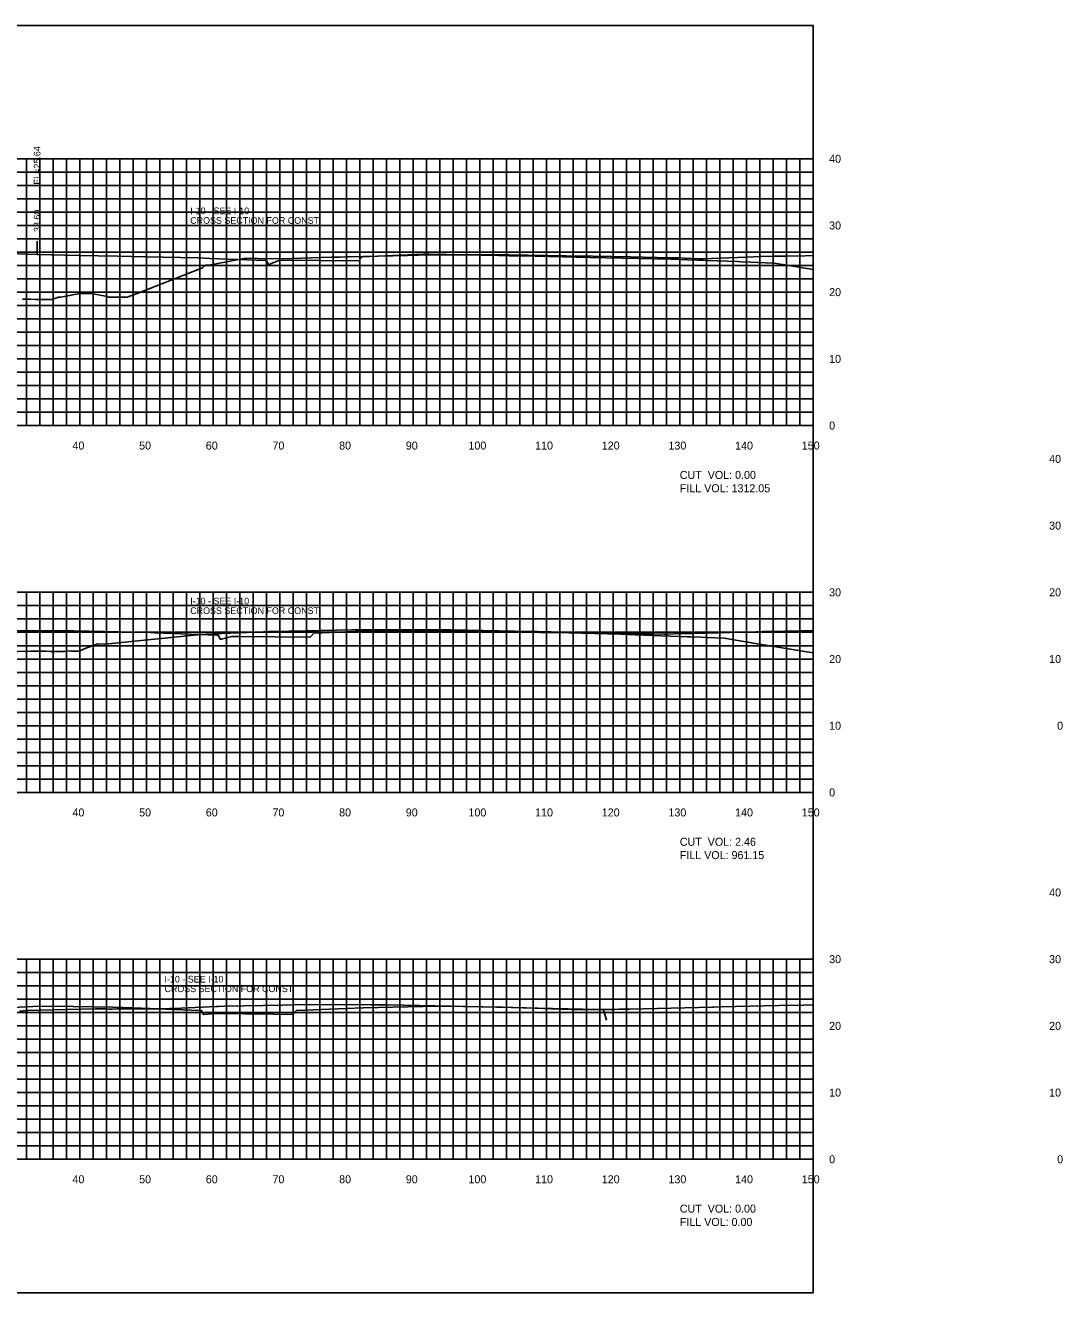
# Model space of a CAD drawing. Extents: x 1797518 to 1804843, y 248068 to 251132.
# Drawn here: x 1802322.8 to 1802478.4, y 250079.4 to 250269.4 of the extents above; entities that cross this region are included whole.
import ezdxf

# ---------------------------------------------------------------- set-up
doc = ezdxf.new("R2010")
doc.units = 0
for name, color, linetype in [('10', 7, 'Continuous'), ('3', 7, 'Continuous'), ('31', 7, 'Continuous'), ('60', 7, 'Continuous'), ('ANNO-TXT', 7, 'Continuous'), ('CL-CNST', 7, 'Continuous'), ('Level 62', 7, 'Continuous'), ('M-ROADS', 7, 'Continuous')]:
    doc.layers.add(name, color=color, linetype=linetype)

msp = doc.modelspace()

# ---------------------------------------------------------------- linework, layer by layer
msp.add_line((1802324.6, 250235.07), (1802324.6, 250237.07))
msp.add_lwpolyline([(1802141, 250079.43), (1802441, 250079.43), (1802441, 250269.43), (1802141, 250269.43)], close=True)
at = {"layer": '60'}
for p, q in [((1802441, 250209.43), (1802441, 250249.43)), ((1802441.06, 250249.43), (1802441, 250249.43)), ((1802441.06, 250239.43), (1802441, 250239.43)), ((1802441.06, 250229.43), (1802441, 250229.43)), ((1802441.06, 250219.43), (1802441, 250219.43)), ((1802141, 250209.43), (1802441, 250209.43)), ((1802331, 250209.37), (1802331, 250209.43)), ((1802341, 250209.37), (1802341, 250209.43)), ((1802351, 250209.37), (1802351, 250209.43)), ((1802361, 250209.37), (1802361, 250209.43)), ((1802371, 250209.37), (1802371, 250209.43)), ((1802381, 250209.37), (1802381, 250209.43)), ((1802391, 250209.37), (1802391, 250209.43)), ((1802401, 250209.37), (1802401, 250209.43)), ((1802411, 250209.37), (1802411, 250209.43)), ((1802421, 250209.37), (1802421, 250209.43)), ((1802431, 250209.37), (1802431, 250209.43)), ((1802441, 250209.37), (1802441, 250209.43)), ((1802441.06, 250209.43), (1802441, 250209.43)), ((1802441, 250154.43), (1802441, 250184.43)), ((1802441.06, 250184.43), (1802441, 250184.43)), ((1802441.06, 250174.43), (1802441, 250174.43)), ((1802441.06, 250164.43), (1802441, 250164.43)), ((1802141, 250154.43), (1802441, 250154.43)), ((1802331, 250154.37), (1802331, 250154.43)), ((1802341, 250154.37), (1802341, 250154.43)), ((1802351, 250154.37), (1802351, 250154.43)), ((1802361, 250154.37), (1802361, 250154.43)), ((1802371, 250154.37), (1802371, 250154.43)), ((1802381, 250154.37), (1802381, 250154.43)), ((1802391, 250154.37), (1802391, 250154.43)), ((1802401, 250154.37), (1802401, 250154.43)), ((1802411, 250154.37), (1802411, 250154.43)), ((1802421, 250154.37), (1802421, 250154.43)), ((1802431, 250154.37), (1802431, 250154.43)), ((1802441, 250154.37), (1802441, 250154.43)), ((1802441.06, 250154.43), (1802441, 250154.43)), ((1802441, 250099.43), (1802441, 250129.43)), ((1802441.06, 250129.43), (1802441, 250129.43)), ((1802441.06, 250119.43), (1802441, 250119.43)), ((1802441.06, 250109.43), (1802441, 250109.43)), ((1802141, 250099.43), (1802441, 250099.43)), ((1802331, 250099.37), (1802331, 250099.43)), ((1802341, 250099.37), (1802341, 250099.43)), ((1802351, 250099.37), (1802351, 250099.43)), ((1802361, 250099.37), (1802361, 250099.43)), ((1802371, 250099.37), (1802371, 250099.43)), ((1802381, 250099.37), (1802381, 250099.43)), ((1802391, 250099.37), (1802391, 250099.43)), ((1802401, 250099.37), (1802401, 250099.43)), ((1802411, 250099.37), (1802411, 250099.43)), ((1802421, 250099.37), (1802421, 250099.43)), ((1802431, 250099.37), (1802431, 250099.43)), ((1802441, 250099.37), (1802441, 250099.43)), ((1802441.06, 250099.43), (1802441, 250099.43))]:
    msp.add_line(p, q, dxfattribs=at)
at = {"layer": 'CL-CNST'}
for points in [[(1802257.69, 250228.09), (1802281, 250233.91), (1802283, 250233.99), (1802291, 250234.31), (1802315, 250235.21), (1802319, 250235.3), (1802324.6, 250235.07)], [(1802324.6, 250235.07), (1802330.86, 250234.94), (1802336.66, 250234.82), (1802340.83, 250234.74), (1802348.73, 250234.57), (1802350.5, 250234.5), (1802358.78, 250234.19), (1802358.78, 250234.19), (1802358.99, 250234.18), (1802359, 250234.16), (1802359.32, 250233.57), (1802359.36, 250233.59), (1802360.59, 250234.06), (1802361.04, 250234.23), (1802361.04, 250234.23), (1802361.06, 250234.23), (1802372.81, 250234.12), (1802373.32, 250234.7), (1802373.35, 250234.73), (1802382.52, 250235.11), (1802383.41, 250235.14), (1802393.85, 250234.93), (1802395.47, 250234.89), (1802397.26, 250234.86), (1802407.53, 250234.65), (1802409.94, 250234.6), (1802419.59, 250234.4), (1802422.1, 250234.3), (1802429.65, 250234.01), (1802430.21, 250233.99), (1802431.66, 250233.93), (1802432.69, 250233.89), (1802435.18, 250233.8), (1802441, 250232.84)], [(1802317.54, 250178.67), (1802329.54, 250178.65), (1802330.1, 250178.63), (1802341.55, 250178.39), (1802342.26, 250178.36), (1802351.56, 250178), (1802351.58, 250177.99), (1802351.8, 250177.99), (1802351.82, 250177.93), (1802352.11, 250177.38), (1802352.26, 250177.43), (1802353.82, 250177.81), (1802354.95, 250177.79), (1802365.54, 250177.69), (1802365.6, 250177.76), (1802366.08, 250178.3), (1802367.29, 250178.35), (1802376.09, 250178.71), (1802377.8, 250178.7), (1802388.11, 250178.68), (1802390.11, 250178.64), (1802400.12, 250178.42), (1802402.41, 250178.38), (1802412.14, 250178.17), (1802414.28, 250178.08), (1802422.15, 250177.77), (1802422.61, 250177.76), (1802424.15, 250177.7), (1802424.98, 250177.66), (1802427.66, 250177.56), (1802432.94, 250176.68), (1802441, 250175.34)], [(1802315, 250121.89), (1802323.96, 250122.34), (1802327, 250122.4), (1802335.96, 250122.21), (1802339, 250122.14), (1802346.47, 250121.84), (1802349, 250121.74), (1802349.19, 250121.73), (1802349.25, 250121.73), (1802349.47, 250121.28), (1802349.54, 250121.13), (1802350.82, 250121.22), (1802351.25, 250121.26), (1802359.99, 250121.16), (1802362.96, 250121.13), (1802363.1, 250121.29), (1802363.5, 250121.75), (1802370.97, 250122.04), (1802373.5, 250122.15), (1802382.46, 250122.34), (1802385.5, 250122.4), (1802394.46, 250122.21), (1802397.5, 250122.14), (1802406.46, 250121.94), (1802409.5, 250121.88), (1802409.63, 250121.47), (1802410.01, 250120.28)]]:
    msp.add_lwpolyline(points, dxfattribs=at)
at = {"layer": 'Level 62'}
for p, q in [((1802141, 250249.43), (1802441, 250249.43)), ((1802323, 250209.43), (1802323, 250249.43)), ((1802325, 250209.43), (1802325, 250249.43)), ((1802327, 250209.43), (1802327, 250249.43)), ((1802329, 250209.43), (1802329, 250249.43)), ((1802331, 250209.43), (1802331, 250249.43)), ((1802333, 250209.43), (1802333, 250249.43)), ((1802335, 250209.43), (1802335, 250249.43)), ((1802337, 250209.43), (1802337, 250249.43)), ((1802339, 250209.43), (1802339, 250249.43)), ((1802341, 250209.43), (1802341, 250249.43)), ((1802343, 250209.43), (1802343, 250249.43)), ((1802345, 250209.43), (1802345, 250249.43)), ((1802347, 250209.43), (1802347, 250249.43)), ((1802349, 250209.43), (1802349, 250249.43)), ((1802351, 250209.43), (1802351, 250249.43)), ((1802353, 250209.43), (1802353, 250249.43)), ((1802355, 250209.43), (1802355, 250249.43)), ((1802357, 250209.43), (1802357, 250249.43)), ((1802359, 250209.43), (1802359, 250249.43)), ((1802361, 250209.43), (1802361, 250249.43)), ((1802363, 250209.43), (1802363, 250249.43)), ((1802365, 250209.43), (1802365, 250249.43)), ((1802367, 250209.43), (1802367, 250249.43)), ((1802369, 250209.43), (1802369, 250249.43)), ((1802371, 250209.43), (1802371, 250249.43)), ((1802373, 250209.43), (1802373, 250249.43)), ((1802375, 250209.43), (1802375, 250249.43)), ((1802377, 250209.43), (1802377, 250249.43)), ((1802379, 250209.43), (1802379, 250249.43)), ((1802381, 250209.43), (1802381, 250249.43)), ((1802383, 250209.43), (1802383, 250249.43)), ((1802385, 250209.43), (1802385, 250249.43)), ((1802387, 250209.43), (1802387, 250249.43)), ((1802389, 250209.43), (1802389, 250249.43)), ((1802391, 250209.43), (1802391, 250249.43)), ((1802393, 250209.43), (1802393, 250249.43)), ((1802395, 250209.43), (1802395, 250249.43)), ((1802397, 250209.43), (1802397, 250249.43)), ((1802399, 250209.43), (1802399, 250249.43)), ((1802401, 250209.43), (1802401, 250249.43)), ((1802403, 250209.43), (1802403, 250249.43)), ((1802405, 250209.43), (1802405, 250249.43)), ((1802407, 250209.43), (1802407, 250249.43)), ((1802409, 250209.43), (1802409, 250249.43)), ((1802411, 250209.43), (1802411, 250249.43)), ((1802413, 250209.43), (1802413, 250249.43)), ((1802415, 250209.43), (1802415, 250249.43)), ((1802417, 250209.43), (1802417, 250249.43)), ((1802419, 250209.43), (1802419, 250249.43)), ((1802421, 250209.43), (1802421, 250249.43)), ((1802423, 250209.43), (1802423, 250249.43)), ((1802425, 250209.43), (1802425, 250249.43)), ((1802427, 250209.43), (1802427, 250249.43)), ((1802429, 250209.43), (1802429, 250249.43)), ((1802431, 250209.43), (1802431, 250249.43)), ((1802433, 250209.43), (1802433, 250249.43)), ((1802435, 250209.43), (1802435, 250249.43)), ((1802437, 250209.43), (1802437, 250249.43)), ((1802439, 250209.43), (1802439, 250249.43)), ((1802441, 250209.43), (1802441, 250249.43)), ((1802141, 250247.43), (1802441, 250247.43)), ((1802141, 250245.43), (1802441, 250245.43)), ((1802141, 250243.43), (1802441, 250243.43)), ((1802141, 250241.43), (1802441, 250241.43)), ((1802141, 250239.43), (1802441, 250239.43)), ((1802141, 250237.43), (1802441, 250237.43)), ((1802141, 250235.43), (1802441, 250235.43)), ((1802141, 250233.43), (1802441, 250233.43)), ((1802141, 250231.43), (1802441, 250231.43)), ((1802141, 250229.43), (1802441, 250229.43)), ((1802141, 250227.43), (1802441, 250227.43)), ((1802141, 250225.43), (1802441, 250225.43)), ((1802141, 250223.43), (1802441, 250223.43)), ((1802141, 250221.43), (1802441, 250221.43)), ((1802141, 250219.43), (1802441, 250219.43)), ((1802141, 250217.43), (1802441, 250217.43)), ((1802141, 250215.43), (1802441, 250215.43)), ((1802141, 250213.43), (1802441, 250213.43)), ((1802141, 250211.43), (1802441, 250211.43)), ((1802141, 250209.43), (1802441, 250209.43)), ((1802141, 250184.43), (1802441, 250184.43)), ((1802323, 250154.43), (1802323, 250184.43)), ((1802325, 250154.43), (1802325, 250184.43)), ((1802327, 250154.43), (1802327, 250184.43)), ((1802329, 250154.43), (1802329, 250184.43)), ((1802331, 250154.43), (1802331, 250184.43)), ((1802333, 250154.43), (1802333, 250184.43)), ((1802335, 250154.43), (1802335, 250184.43)), ((1802337, 250154.43), (1802337, 250184.43)), ((1802339, 250154.43), (1802339, 250184.43)), ((1802341, 250154.43), (1802341, 250184.43)), ((1802343, 250154.43), (1802343, 250184.43)), ((1802345, 250154.43), (1802345, 250184.43)), ((1802347, 250154.43), (1802347, 250184.43)), ((1802349, 250154.43), (1802349, 250184.43)), ((1802351, 250154.43), (1802351, 250184.43)), ((1802353, 250154.43), (1802353, 250184.43)), ((1802355, 250154.43), (1802355, 250184.43)), ((1802357, 250154.43), (1802357, 250184.43)), ((1802359, 250154.43), (1802359, 250184.43)), ((1802361, 250154.43), (1802361, 250184.43)), ((1802363, 250154.43), (1802363, 250184.43)), ((1802365, 250154.43), (1802365, 250184.43)), ((1802367, 250154.43), (1802367, 250184.43)), ((1802369, 250154.43), (1802369, 250184.43)), ((1802371, 250154.43), (1802371, 250184.43)), ((1802373, 250154.43), (1802373, 250184.43)), ((1802375, 250154.43), (1802375, 250184.43)), ((1802377, 250154.43), (1802377, 250184.43)), ((1802379, 250154.43), (1802379, 250184.43)), ((1802381, 250154.43), (1802381, 250184.43)), ((1802383, 250154.43), (1802383, 250184.43)), ((1802385, 250154.43), (1802385, 250184.43)), ((1802387, 250154.43), (1802387, 250184.43)), ((1802389, 250154.43), (1802389, 250184.43)), ((1802391, 250154.43), (1802391, 250184.43)), ((1802393, 250154.43), (1802393, 250184.43)), ((1802395, 250154.43), (1802395, 250184.43)), ((1802397, 250154.43), (1802397, 250184.43)), ((1802399, 250154.43), (1802399, 250184.43)), ((1802401, 250154.43), (1802401, 250184.43)), ((1802403, 250154.43), (1802403, 250184.43)), ((1802405, 250154.43), (1802405, 250184.43)), ((1802407, 250154.43), (1802407, 250184.43)), ((1802409, 250154.43), (1802409, 250184.43)), ((1802411, 250154.43), (1802411, 250184.43)), ((1802413, 250154.43), (1802413, 250184.43)), ((1802415, 250154.43), (1802415, 250184.43)), ((1802417, 250154.43), (1802417, 250184.43)), ((1802419, 250154.43), (1802419, 250184.43)), ((1802421, 250154.43), (1802421, 250184.43)), ((1802423, 250154.43), (1802423, 250184.43)), ((1802425, 250154.43), (1802425, 250184.43)), ((1802427, 250154.43), (1802427, 250184.43)), ((1802429, 250154.43), (1802429, 250184.43)), ((1802431, 250154.43), (1802431, 250184.43)), ((1802433, 250154.43), (1802433, 250184.43)), ((1802435, 250154.43), (1802435, 250184.43)), ((1802437, 250154.43), (1802437, 250184.43)), ((1802439, 250154.43), (1802439, 250184.43)), ((1802441, 250154.43), (1802441, 250184.43)), ((1802141, 250182.43), (1802441, 250182.43)), ((1802141, 250180.43), (1802441, 250180.43)), ((1802141, 250178.43), (1802441, 250178.43)), ((1802141, 250176.43), (1802441, 250176.43)), ((1802141, 250174.43), (1802441, 250174.43)), ((1802141, 250172.43), (1802441, 250172.43)), ((1802141, 250170.43), (1802441, 250170.43)), ((1802141, 250168.43), (1802441, 250168.43)), ((1802141, 250166.43), (1802441, 250166.43)), ((1802141, 250164.43), (1802441, 250164.43)), ((1802141, 250162.43), (1802441, 250162.43)), ((1802141, 250160.43), (1802441, 250160.43)), ((1802141, 250158.43), (1802441, 250158.43)), ((1802141, 250156.43), (1802441, 250156.43)), ((1802141, 250154.43), (1802441, 250154.43)), ((1802141, 250129.43), (1802441, 250129.43)), ((1802323, 250099.43), (1802323, 250129.43)), ((1802325, 250099.43), (1802325, 250129.43)), ((1802327, 250099.43), (1802327, 250129.43)), ((1802329, 250099.43), (1802329, 250129.43)), ((1802331, 250099.43), (1802331, 250129.43)), ((1802333, 250099.43), (1802333, 250129.43)), ((1802335, 250099.43), (1802335, 250129.43)), ((1802337, 250099.43), (1802337, 250129.43)), ((1802339, 250099.43), (1802339, 250129.43)), ((1802341, 250099.43), (1802341, 250129.43)), ((1802343, 250099.43), (1802343, 250129.43)), ((1802345, 250099.43), (1802345, 250129.43)), ((1802347, 250099.43), (1802347, 250129.43)), ((1802349, 250099.43), (1802349, 250129.43)), ((1802351, 250099.43), (1802351, 250129.43)), ((1802353, 250099.43), (1802353, 250129.43)), ((1802355, 250099.43), (1802355, 250129.43)), ((1802357, 250099.43), (1802357, 250129.43)), ((1802359, 250099.43), (1802359, 250129.43)), ((1802361, 250099.43), (1802361, 250129.43)), ((1802363, 250099.43), (1802363, 250129.43)), ((1802365, 250099.43), (1802365, 250129.43)), ((1802367, 250099.43), (1802367, 250129.43)), ((1802369, 250099.43), (1802369, 250129.43)), ((1802371, 250099.43), (1802371, 250129.43)), ((1802373, 250099.43), (1802373, 250129.43)), ((1802375, 250099.43), (1802375, 250129.43)), ((1802377, 250099.43), (1802377, 250129.43)), ((1802379, 250099.43), (1802379, 250129.43)), ((1802381, 250099.43), (1802381, 250129.43)), ((1802383, 250099.43), (1802383, 250129.43)), ((1802385, 250099.43), (1802385, 250129.43)), ((1802387, 250099.43), (1802387, 250129.43)), ((1802389, 250099.43), (1802389, 250129.43)), ((1802391, 250099.43), (1802391, 250129.43)), ((1802393, 250099.43), (1802393, 250129.43)), ((1802395, 250099.43), (1802395, 250129.43)), ((1802397, 250099.43), (1802397, 250129.43)), ((1802399, 250099.43), (1802399, 250129.43)), ((1802401, 250099.43), (1802401, 250129.43)), ((1802403, 250099.43), (1802403, 250129.43)), ((1802405, 250099.43), (1802405, 250129.43)), ((1802407, 250099.43), (1802407, 250129.43)), ((1802409, 250099.43), (1802409, 250129.43)), ((1802411, 250099.43), (1802411, 250129.43)), ((1802413, 250099.43), (1802413, 250129.43)), ((1802415, 250099.43), (1802415, 250129.43)), ((1802417, 250099.43), (1802417, 250129.43)), ((1802419, 250099.43), (1802419, 250129.43)), ((1802421, 250099.43), (1802421, 250129.43)), ((1802423, 250099.43), (1802423, 250129.43)), ((1802425, 250099.43), (1802425, 250129.43)), ((1802427, 250099.43), (1802427, 250129.43)), ((1802429, 250099.43), (1802429, 250129.43)), ((1802431, 250099.43), (1802431, 250129.43)), ((1802433, 250099.43), (1802433, 250129.43)), ((1802435, 250099.43), (1802435, 250129.43)), ((1802437, 250099.43), (1802437, 250129.43)), ((1802439, 250099.43), (1802439, 250129.43)), ((1802441, 250099.43), (1802441, 250129.43)), ((1802141, 250127.43), (1802441, 250127.43)), ((1802141, 250125.43), (1802441, 250125.43)), ((1802141, 250123.43), (1802441, 250123.43)), ((1802141, 250121.43), (1802441, 250121.43)), ((1802141, 250119.43), (1802441, 250119.43)), ((1802141, 250117.43), (1802441, 250117.43)), ((1802141, 250115.43), (1802441, 250115.43)), ((1802141, 250113.43), (1802441, 250113.43)), ((1802141, 250111.43), (1802441, 250111.43)), ((1802141, 250109.43), (1802441, 250109.43)), ((1802141, 250107.43), (1802441, 250107.43)), ((1802141, 250105.43), (1802441, 250105.43)), ((1802141, 250103.43), (1802441, 250103.43)), ((1802141, 250101.43), (1802441, 250101.43)), ((1802141, 250099.43), (1802441, 250099.43))]:
    msp.add_line(p, q, dxfattribs=at)
at = {"layer": 'M-ROADS'}
for points in [[(1802322.4, 250228.4), (1802323.49, 250228.39), (1802323.66, 250228.38), (1802324.36, 250228.35), (1802324.49, 250228.32), (1802324.97, 250228.31), (1802325.93, 250228.34), (1802326.3, 250228.34), (1802326.87, 250228.35), (1802327.81, 250228.68), (1802328.16, 250228.69), (1802330.99, 250229.21), (1802331.76, 250229.22), (1802332.76, 250229.22), (1802335.1, 250228.8), (1802335.37, 250228.66), (1802335.85, 250228.66), (1802337.62, 250228.69), (1802338.12, 250228.69), (1802339.59, 250229.23), (1802349.39, 250233.1), (1802349.87, 250233.5), (1802350.64, 250233.53), (1802355.36, 250234.43), (1802355.9, 250234.52), (1802357.67, 250234.48), (1802361.29, 250234.42), (1802368.71, 250234.66), (1802370.06, 250234.7), (1802370.9, 250234.73), (1802371.28, 250234.74), (1802371.32, 250234.74), (1802380.14, 250234.95), (1802383.34, 250235.03), (1802388.01, 250235.04), (1802394.92, 250235.03), (1802395.2, 250235.03), (1802395.39, 250235.03), (1802403.93, 250234.89), (1802407.97, 250234.82), (1802413.55, 250234.71), (1802419.57, 250234.6), (1802420.35, 250234.58), (1802420.82, 250234.56), (1802421.68, 250234.53), (1802423.87, 250234.42), (1802424.48, 250234.44), (1802425.7, 250234.48), (1802431, 250234.68), (1802433.15, 250234.76), (1802434.95, 250234.81), (1802437.17, 250234.85), (1802439.78, 250234.89), (1802441, 250234.91)], [(1802319.71, 250175.52), (1802323.66, 250175.59), (1802324.67, 250175.61), (1802325.73, 250175.62), (1802325.92, 250175.62), (1802326.61, 250175.58), (1802327.14, 250175.57), (1802328.02, 250175.57), (1802328.39, 250175.57), (1802328.68, 250175.57), (1802329.28, 250175.64), (1802329.68, 250175.62), (1802330.59, 250175.63), (1802330.93, 250175.63), (1802331.66, 250175.97), (1802333.7, 250176.71), (1802334.73, 250176.67), (1802349.15, 250178.11), (1802349.83, 250178.18), (1802352.31, 250178.27), (1802358.56, 250178.5), (1802359.33, 250178.54), (1802359.81, 250178.55), (1802364.86, 250178.67), (1802371.8, 250178.82), (1802376.55, 250178.81), (1802383.82, 250178.82), (1802386.64, 250178.78), (1802396.28, 250178.6), (1802399.65, 250178.53), (1802407.82, 250178.36), (1802408.59, 250178.33), (1802409.07, 250178.31), (1802411.33, 250178.22), (1802412.11, 250178.19), (1802413.27, 250178.19), (1802416.73, 250178.19), (1802418.58, 250178.18), (1802419.2, 250178.18), (1802420.12, 250178.21), (1802422.97, 250178.28), (1802430.44, 250178.47), (1802432.41, 250178.52), (1802433.42, 250178.54), (1802433.62, 250178.55), (1802434.67, 250178.57), (1802441, 250178.7)], [(1802321.94, 250121.63), (1802323.07, 250121.72), (1802323.2, 250121.73), (1802329.08, 250121.86), (1802333.34, 250121.97), (1802334.25, 250121.99), (1802334.59, 250122), (1802335.02, 250121.99), (1802335.39, 250121.95), (1802335.85, 250121.94), (1802336.55, 250121.96), (1802337.11, 250121.98), (1802338.12, 250121.97), (1802338.36, 250121.97), (1802339.37, 250122), (1802339.6, 250122), (1802339.62, 250122), (1802339.68, 250122), (1802342.74, 250121.98), (1802346.19, 250122.1), (1802351.44, 250122.31), (1802351.78, 250122.32), (1802352.69, 250122.36), (1802361.4, 250122.55), (1802364.7, 250122.61), (1802374.72, 250122.58), (1802376.71, 250122.57), (1802377.18, 250122.56), (1802389.07, 250122.35), (1802397.9, 250122.11), (1802400.56, 250122.04), (1802401.66, 250121.99), (1802401.81, 250121.98), (1802404.67, 250121.87), (1802404.83, 250121.86), (1802405.13, 250121.86), (1802407.05, 250121.87), (1802411.24, 250121.9), (1802411.9, 250121.91), (1802413.48, 250121.95), (1802415.51, 250122), (1802421.76, 250122.14), (1802425.92, 250122.24), (1802426.04, 250122.24), (1802427.17, 250122.28), (1802435.91, 250122.47), (1802439.58, 250122.54), (1802441, 250122.56)]]:
    msp.add_lwpolyline(points, dxfattribs=at)

# ---------------------------------------------------------------- texts
at = {"layer": '10'}
for s, p in [('40', (1802329.9, 250205.83)), ('50', (1802339.9, 250205.83)), ('60', (1802349.9, 250205.83)), ('70', (1802359.9, 250205.83)), ('80', (1802369.9, 250205.83)), ('90', (1802379.9, 250205.83)), ('100', (1802389.3, 250205.83)), ('110', (1802399.3, 250205.83)), ('120', (1802409.3, 250205.83)), ('130', (1802419.3, 250205.83)), ('140', (1802429.3, 250205.83)), ('150', (1802439.3, 250205.83)), ('40', (1802329.9, 250150.83)), ('50', (1802339.9, 250150.83)), ('60', (1802349.9, 250150.83)), ('70', (1802359.9, 250150.83)), ('80', (1802369.9, 250150.83)), ('90', (1802379.9, 250150.83)), ('100', (1802389.3, 250150.83)), ('110', (1802399.3, 250150.83)), ('120', (1802409.3, 250150.83)), ('130', (1802419.3, 250150.83)), ('140', (1802429.3, 250150.83)), ('150', (1802439.3, 250150.83)), ('40', (1802329.9, 250095.83)), ('50', (1802339.9, 250095.83)), ('60', (1802349.9, 250095.83)), ('70', (1802359.9, 250095.83)), ('80', (1802369.9, 250095.83)), ('90', (1802379.9, 250095.83)), ('100', (1802389.3, 250095.83)), ('110', (1802399.3, 250095.83)), ('120', (1802409.3, 250095.83)), ('130', (1802419.3, 250095.83)), ('140', (1802429.3, 250095.83)), ('150', (1802439.3, 250095.83))]:
    msp.add_text(s, height=1.2, dxfattribs=at).set_placement(p)
at = {"layer": '3'}
for s, p in [('EL=25.64', (1802325.1, 250245.54)), ('33.60', (1802325.1, 250238.44))]:
    msp.add_text(s, height=1, rotation=90, dxfattribs=at).set_placement(p)
for s, p in [('I-10 - SEE I-10', (1802347.56, 250241.12)), ('CROSS SECTION FOR CONST ', (1802347.56, 250239.68)), ('I-10 - SEE I-10', (1802347.56, 250182.62)), ('CROSS SECTION FOR CONST ', (1802347.56, 250181.18)), ('CROSS SECTION FOR CONST ', (1802343.7, 250124.49)), ('I-10 - SEE I-10', (1802343.7, 250125.93))]:
    msp.add_text(s, height=1, dxfattribs=at).set_placement(p)
at = {"layer": '31'}
for s, p in [('40', (1802443.4, 250248.83)), ('30', (1802443.4, 250238.83)), ('20', (1802443.4, 250228.83)), ('10', (1802443.4, 250218.83)), ('0', (1802443.4, 250208.83)), ('40', (1802476.4, 250203.83)), ('30', (1802476.4, 250193.83)), ('30', (1802443.4, 250183.83)), ('20', (1802476.4, 250183.83)), ('20', (1802443.4, 250173.83)), ('10', (1802476.4, 250173.83)), ('10', (1802443.4, 250163.83)), ('0', (1802477.6, 250163.83)), ('0', (1802443.4, 250153.83)), ('40', (1802476.4, 250138.83)), ('30', (1802443.4, 250128.83)), ('30', (1802476.4, 250128.83)), ('20', (1802443.4, 250118.83)), ('20', (1802476.4, 250118.83)), ('10', (1802443.4, 250108.83)), ('10', (1802476.4, 250108.83)), ('0', (1802443.4, 250098.83)), ('0', (1802477.6, 250098.83))]:
    msp.add_text(s, height=1.2, dxfattribs=at).set_placement(p)
at = {"layer": 'ANNO-TXT'}
for s, p in [('CUT  VOL: 0.00', (1802421, 250201.43)), ('FILL VOL: 1312.05', (1802421, 250199.43)), ('CUT  VOL: 2.46', (1802421, 250146.43)), ('FILL VOL: 961.15', (1802421, 250144.43)), ('CUT  VOL: 0.00', (1802421, 250091.43)), ('FILL VOL: 0.00', (1802421, 250089.43))]:
    msp.add_text(s, height=1.2, dxfattribs=at).set_placement(p)

doc.saveas('drawing.dxf')
